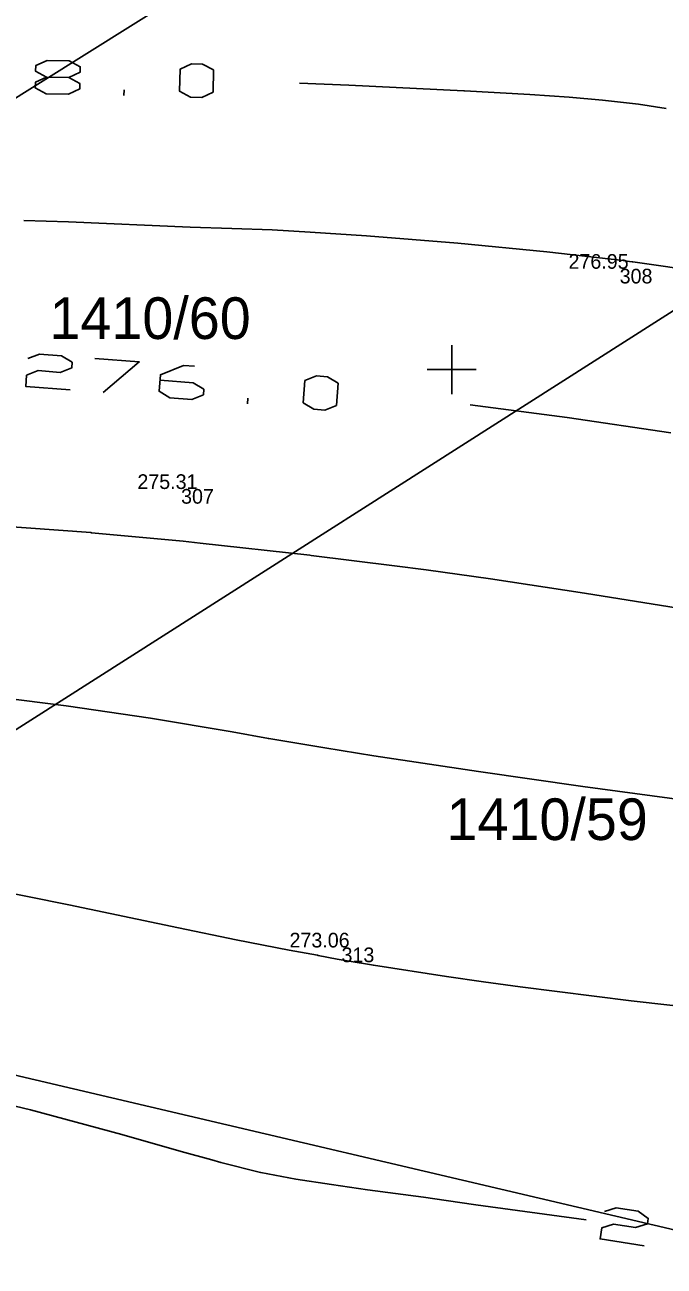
# Model space of a CAD drawing. Extents: x -771260 to -770828, y -1053564 to -1052811.
# Drawn here: x -771067.4 to -771041.3, y -1053186.6 to -1053135.9 of the extents above; entities that cross this region are included whole.
import ezdxf

# ---------------------------------------------------------------- set-up
doc = ezdxf.new("R2010")
doc.units = 0
for name, color, linetype in [('14_8_2023_krizky', 7, 'Continuous'), ('25_3_2019_krizky_JTSK', 7, 'Continuous'), ('25_3_2019_vrstevnice_interval_po_1m', 7, 'Continuous'), ('25_3_2019_zamereny_bod', 7, 'Continuous'), ('25_3_2019_zamereny_bod_cislo', 7, 'Continuous'), ('25_3_2019_zamereny_bod_vyska', 7, 'Continuous'), ('Default', 7, 'Continuous'), ('DKM_Hranice parcel', 7, 'Continuous'), ('DKM_Parcelní čísla', 7, 'Continuous')]:
    doc.layers.add(name, color=color, linetype=linetype)

# ---------------------------------------------------------------- blocks, each defined once
blk = doc.blocks.new('POINT_DISPLAY')
at = {"layer": 'Default'}
blk.add_line((0, 0), (0, 0), dxfattribs=at)
blk = doc.blocks.new('KRIZEK')
at = {"layer": '25_3_2019_krizky_JTSK'}
for p, q in [((0, 10), (0, -10)), ((-10, 0), (10, 0))]:
    blk.add_line(p, q, dxfattribs=at)

msp = doc.modelspace()

# ---------------------------------------------------------------- linework, layer by layer
at = {"layer": '25_3_2019_vrstevnice_interval_po_1m'}
for points in [[(-771065.637, -1053138.069), (-771065.178, -1053137.853), (-771065.173, -1053137.626), (-771065.621, -1053137.388), (-771066.528, -1053137.366), (-771066.988, -1053137.582), (-771066.993, -1053137.809), (-771066.545, -1053138.047)], [(-771060.662, -1053138.869), (-771061.111, -1053138.631), (-771061.089, -1053137.724), (-771060.63, -1053137.508), (-771060.176, -1053137.519), (-771059.728, -1053137.756), (-771059.749, -1053138.664), (-771060.209, -1053138.88), (-771060.662, -1053138.869)], [(-771065.637, -1053138.069), (-771065.189, -1053138.306), (-771065.194, -1053138.533), (-771065.653, -1053138.749), (-771066.561, -1053138.728), (-771067.009, -1053138.49), (-771067.004, -1053138.263), (-771066.545, -1053138.047)], [(-771066.545, -1053138.047), (-771065.637, -1053138.069)], [(-771063.385, -1053138.804), (-771063.379, -1053138.577)], [(-771056.21, -1053138.295), (-771056.21, -1053138.295)], [(-771056.21, -1053138.295), (-771054.208, -1053138.375), (-771049.507, -1053138.613), (-771049.482, -1053138.614), (-771046.81, -1053138.763), (-771045.198, -1053138.873), (-771043.846, -1053138.987), (-771042.372, -1053139.15), (-771042.369, -1053139.15), (-771041.241, -1053139.334)], [(-771054.208, -1053138.375), (-771054.208, -1053138.375)], [(-771049.482, -1053138.614), (-771049.482, -1053138.614)], [(-771046.81, -1053138.763), (-771046.81, -1053138.763)], [(-771045.198, -1053138.873), (-771045.198, -1053138.873)], [(-771043.846, -1053138.987), (-771043.846, -1053138.987)], [(-771042.369, -1053139.15), (-771042.369, -1053139.15)], [(-771067.472, -1053143.903), (-771065.656, -1053143.968), (-771060.682, -1053144.182), (-771058.983, -1053144.238), (-771057.331, -1053144.293), (-771055.777, -1053144.379), (-771053.474, -1053144.529), (-771049.749, -1053144.832), (-771046.121, -1053145.185), (-771043.489, -1053145.484), (-771043.101, -1053145.528), (-771043.098, -1053145.528), (-771042.737, -1053145.584), (-771042.632, -1053145.6), (-771042.603, -1053145.604), (-771041.368, -1053145.77), (-771037.931, -1053146.275), (-771033.815, -1053146.924), (-771029.378, -1053147.652), (-771027.379, -1053147.966)], [(-771065.656, -1053143.968), (-771065.656, -1053143.968)], [(-771060.682, -1053144.182), (-771060.682, -1053144.182)], [(-771057.331, -1053144.293), (-771057.331, -1053144.293)], [(-771055.777, -1053144.379), (-771055.777, -1053144.379)], [(-771053.474, -1053144.529), (-771053.474, -1053144.529)], [(-771049.749, -1053144.832), (-771049.749, -1053144.832)], [(-771046.121, -1053145.185), (-771046.121, -1053145.185)], [(-771043.098, -1053145.528), (-771043.098, -1053145.528)], [(-771042.632, -1053145.6), (-771042.632, -1053145.6)], [(-771041.368, -1053145.77), (-771041.368, -1053145.77)], [(-771067.305, -1053149.553), (-771066.835, -1053149.363), (-771065.93, -1053149.435), (-771065.496, -1053149.697), (-771065.514, -1053149.923), (-771065.984, -1053150.113), (-771066.889, -1053150.042), (-771067.359, -1053150.232), (-771067.395, -1053150.684), (-771065.585, -1053150.828)], [(-771064.573, -1053149.542), (-771062.763, -1053149.685), (-771064.228, -1053150.935)], [(-771061.912, -1053150.435), (-771060.554, -1053150.543), (-771060.12, -1053150.805), (-771060.138, -1053151.031), (-771060.608, -1053151.222), (-771061.513, -1053151.15), (-771061.948, -1053150.888), (-771061.894, -1053150.209), (-771060.953, -1053149.828), (-771060.501, -1053149.864)], [(-771055.631, -1053151.616), (-771056.066, -1053151.353), (-771055.994, -1053150.449), (-771055.524, -1053150.258), (-771055.071, -1053150.294), (-771054.637, -1053150.556), (-771054.708, -1053151.461), (-771055.179, -1053151.651), (-771055.631, -1053151.616)], [(-771058.346, -1053151.401), (-771058.328, -1053151.174)], [(-771049.244, -1053151.438), (-771049.244, -1053151.438)], [(-771049.244, -1053151.438), (-771045.29, -1053151.962), (-771041.05, -1053152.585)], [(-771045.29, -1053151.962), (-771045.29, -1053151.962)], [(-771068.71, -1053156.369), (-771064.74, -1053156.662), (-771064.707, -1053156.665), (-771060.973, -1053157.014), (-771060.278, -1053157.09), (-771055.796, -1053157.584), (-771055.736, -1053157.591), (-771052.335, -1053158.011), (-771051.047, -1053158.183), (-771048.42, -1053158.555), (-771044.582, -1053159.137), (-771038.714, -1053160.077)], [(-771064.74, -1053156.662), (-771064.74, -1053156.662)], [(-771060.973, -1053157.014), (-771060.973, -1053157.014)], [(-771055.736, -1053157.591), (-771055.736, -1053157.591)], [(-771052.335, -1053158.011), (-771052.335, -1053158.011)], [(-771051.047, -1053158.183), (-771051.047, -1053158.183)], [(-771048.42, -1053158.555), (-771048.42, -1053158.555)], [(-771044.582, -1053159.137), (-771044.582, -1053159.137)], [(-771069.305, -1053163.281), (-771065.74, -1053163.731), (-771062.307, -1053164.247), (-771058.964, -1053164.806), (-771057.487, -1053165.072), (-771057.473, -1053165.074), (-771055.186, -1053165.454), (-771053.18, -1053165.778), (-771048.908, -1053166.423), (-771044.647, -1053167.033), (-771040.4, -1053167.607)], [(-771065.74, -1053163.731), (-771065.74, -1053163.731)], [(-771062.307, -1053164.247), (-771062.307, -1053164.247)], [(-771058.964, -1053164.806), (-771058.964, -1053164.806)], [(-771057.473, -1053165.074), (-771057.473, -1053165.074)], [(-771055.186, -1053165.454), (-771055.186, -1053165.454)], [(-771053.18, -1053165.778), (-771053.18, -1053165.778)], [(-771048.908, -1053166.423), (-771048.908, -1053166.423)], [(-771044.647, -1053167.033), (-771044.647, -1053167.033)], [(-771069.029, -1053171.187), (-771065.631, -1053171.868), (-771061.152, -1053172.807), (-771058.801, -1053173.292), (-771056.634, -1053173.72), (-771055.487, -1053173.929), (-771055.45, -1053173.936), (-771054.674, -1053174.088), (-771054.672, -1053174.088), (-771054.275, -1053174.155), (-771053.198, -1053174.336), (-771050.208, -1053174.795), (-771048.708, -1053175.013), (-771047.203, -1053175.216), (-771044.186, -1053175.604), (-771042.672, -1053175.785), (-771039.637, -1053176.125)], [(-771065.631, -1053171.868), (-771065.631, -1053171.868)], [(-771061.152, -1053172.807), (-771061.152, -1053172.807)], [(-771058.801, -1053173.292), (-771058.801, -1053173.292)], [(-771056.634, -1053173.72), (-771056.634, -1053173.72)], [(-771055.487, -1053173.929), (-771055.487, -1053173.929)], [(-771054.674, -1053174.088), (-771054.674, -1053174.088)], [(-771053.198, -1053174.336), (-771053.198, -1053174.336)], [(-771050.208, -1053174.795), (-771050.208, -1053174.795)], [(-771048.708, -1053175.013), (-771048.708, -1053175.013)], [(-771047.203, -1053175.216), (-771047.203, -1053175.216)], [(-771044.186, -1053175.604), (-771044.186, -1053175.604)], [(-771042.672, -1053175.785), (-771042.672, -1053175.785)], [(-771070.512, -1053179.447), (-771067.201, -1053180.24), (-771063.471, -1053181.251), (-771061.047, -1053181.949), (-771059.802, -1053182.284), (-771059.431, -1053182.39), (-771057.804, -1053182.8), (-771057.802, -1053182.801), (-771056.364, -1053183.072), (-771054.908, -1053183.299), (-771053.444, -1053183.506), (-771051.146, -1053183.813), (-771050.229, -1053183.947), (-771049.021, -1053184.123), (-771044.509, -1053184.74)], [(-771067.201, -1053180.24), (-771067.201, -1053180.24)], [(-771063.471, -1053181.251), (-771063.471, -1053181.251)], [(-771061.047, -1053181.949), (-771061.047, -1053181.949)], [(-771059.802, -1053182.284), (-771059.802, -1053182.284)], [(-771059.431, -1053182.39), (-771059.431, -1053182.39)], [(-771057.804, -1053182.8), (-771057.804, -1053182.8)], [(-771056.364, -1053183.072), (-771056.364, -1053183.072)], [(-771054.908, -1053183.299), (-771054.908, -1053183.299)], [(-771053.444, -1053183.506), (-771053.444, -1053183.506)], [(-771051.146, -1053183.813), (-771051.146, -1053183.813)], [(-771049.021, -1053184.123), (-771049.021, -1053184.123)], [(-771043.766, -1053184.396), (-771043.283, -1053184.242), (-771042.386, -1053184.382), (-771041.972, -1053184.676), (-771042.007, -1053184.9), (-771042.491, -1053185.054), (-771043.387, -1053184.915), (-771043.871, -1053185.069), (-771043.941, -1053185.518), (-771042.147, -1053185.797)]]:
    msp.add_lwpolyline(points, dxfattribs=at)
at = {"layer": 'DKM_Hranice parcel'}
for p, q in [((-771044.12, -1053124.01), (-771095.9, -1053156.55)), ((-771032.21, -1053142.02), (-771084, -1053175.04)), ((-771034.59, -1053186.63), (-771084, -1053175.04))]:
    msp.add_line(p, q, dxfattribs=at)

# ---------------------------------------------------------------- block references
at = {"layer": '14_8_2023_krizky', "xscale": 0.1, "yscale": 0.10000000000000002}
msp.add_blockref('KRIZEK', (-771050, -1053150), dxfattribs=at)
at = {"layer": '25_3_2019_zamereny_bod', "xscale": 0.1, "yscale": 0.10000000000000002}
for p in [(-771043.141, -1053145.881), (-771061.052, -1053154.878), (-771054.5, -1053173.61)]:
    msp.add_blockref('POINT_DISPLAY', p, dxfattribs=at)

# ---------------------------------------------------------------- texts
at = {"layer": '25_3_2019_zamereny_bod_cislo'}
for s, p in [('308', (-771043.141, -1053146.481)), ('307', (-771061.052, -1053155.478)), ('313', (-771054.5, -1053174.21))]:
    msp.add_text(s, height=0.6, dxfattribs=at).set_placement(p)
at = {"layer": '25_3_2019_zamereny_bod_vyska'}
for s, p in [('276.95 ', (-771045.23, -1053145.881)), ('275.31 ', (-771062.837, -1053154.878)), ('273.06 ', (-771056.624, -1053173.61))]:
    msp.add_text(s, height=0.6, dxfattribs=at).set_placement(p)
at = {"layer": 'DKM_Parcelní čísla'}
for s, p in [('1410/60', (-771066.426, -1053148.749)), ('1410/59', (-771050.21, -1053169.22))]:
    msp.add_text(s, height=1.7, dxfattribs=at).set_placement(p)

doc.saveas('drawing.dxf')
